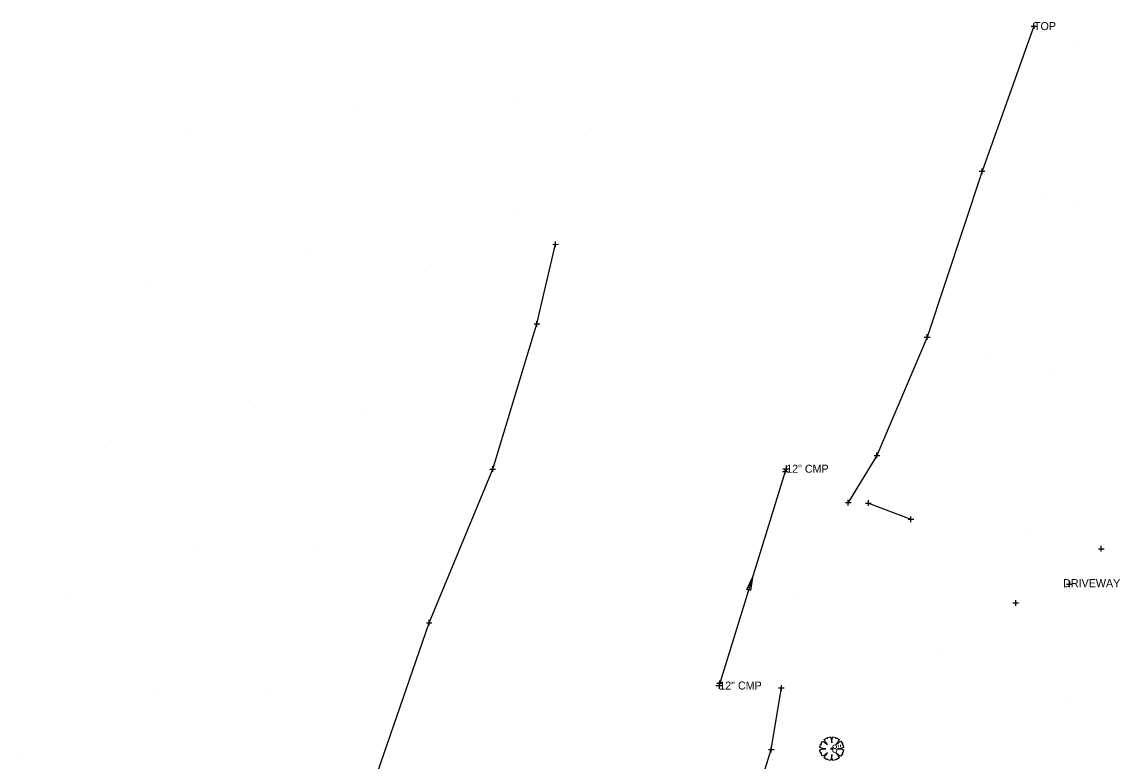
# Model space of a CAD drawing. Extents: x 1733239 to 1734352, y 466612 to 468622.
# Drawn here: x 1733811.3 to 1734058.3, y 467992.2 to 468158.3 of the extents above; entities that cross this region are included whole.
import ezdxf

# ---------------------------------------------------------------- set-up
doc = ezdxf.new("R2010")
doc.units = 0
for name, color, linetype in [('Default', 7, 'Continuous'), ('S_Terrain_Flow_Arrows', 7, 'Continuous'), ('S_Terrain_Holes', 7, 'Continuous'), ('S_Terrain_Imported_Contours', 7, 'Continuous'), ('S_Terrain_Major_Contours', 7, 'Continuous'), ('S_Terrain_Minor_Contours', 7, 'Continuous'), ('S_Terrain_Minor_Contours_Label', 7, 'Continuous'), ('S_Traffic_Sign_SinglePost', 7, 'Continuous'), ('S_Trees_Bush_Line', 7, 'Continuous'), ('S_Utilities_Pole_StreetLight', 7, 'Continuous')]:
    doc.layers.add(name, color=color, linetype=linetype)

msp = doc.modelspace()

# ---------------------------------------------------------------- linework, layer by layer
at = {"layer": 'Default'}
for p, q in [((1733983.22, 468057.92), (1733983.22, 468057.92)), ((1733968.17, 468009.19), (1733968.17, 468009.19))]:
    msp.add_line(p, q, dxfattribs=at)
at = {"layer": 'S_Terrain_Flow_Arrows'}
msp.add_lwpolyline([(1733992.14, 467994.99), (1733991.45, 467995.04), (1733990.81, 467995.25), (1733990.97, 467995.94), (1733991.13, 467995.94), (1733991.08, 467996.16), (1733991.4, 467996.69), (1733991.93, 467996.42), (1733992.51, 467995.94), (1733992.03, 467996.53), (1733991.77, 467997.06), (1733992.3, 467997.38), (1733992.51, 467997.32), (1733992.51, 467997.48), (1733993.2, 467997.64), (1733993.41, 467997), (1733993.47, 467996.31), (1733993.52, 467997), (1733993.73, 467997.64), (1733994.42, 467997.48), (1733994.42, 467997.32), (1733994.63, 467997.38), (1733995.16, 467997.06), (1733994.9, 467996.53), (1733994.42, 467995.94), (1733995, 467996.42), (1733995.53, 467996.69), (1733995.85, 467996.16), (1733995.8, 467995.94), (1733995.96, 467995.94), (1733996.12, 467995.25), (1733995.48, 467995.04), (1733994.79, 467994.99), (1733995.48, 467994.94), (1733996.12, 467994.72), (1733995.96, 467994.03), (1733995.8, 467994.03), (1733995.85, 467993.82), (1733995.53, 467993.29), (1733995, 467993.56), (1733994.42, 467994.03), (1733994.9, 467993.45), (1733995.16, 467992.92), (1733994.63, 467992.6), (1733994.42, 467992.65), (1733994.42, 467992.5), (1733993.73, 467992.34), (1733993.52, 467992.97), (1733993.47, 467993.66), (1733993.41, 467992.97), (1733993.2, 467992.34), (1733992.51, 467992.5), (1733992.51, 467992.65), (1733992.3, 467992.6), (1733991.77, 467992.92), (1733992.03, 467993.45), (1733992.51, 467994.03), (1733991.93, 467993.56), (1733991.4, 467993.29), (1733991.08, 467993.82), (1733991.13, 467994.03), (1733990.97, 467994.03), (1733990.81, 467994.72), (1733991.45, 467994.94), (1733992.14, 467994.99)], dxfattribs=at)
msp.add_circle((1733993.47, 467994.99), 0.166, dxfattribs=at)
at = {"layer": 'S_Terrain_Holes'}
for points in [[(1734038.95, 468157.41), (1734027.27, 468124.78), (1734014.93, 468087.5), (1734003.63, 468060.91), (1733997.18, 468050.3)], [(1733853.36, 467859.67), (1733863.53, 467892.27), (1733873.85, 467924.74), (1733885.4, 467959.39), (1733891.32, 467989.61), (1733902.91, 468023.32), (1733917.22, 468057.86), (1733927.15, 468090.49), (1733931.35, 468108.36)], [(1733949.51, 467895.49), (1733959.79, 467928.95), (1733970.61, 467965.17), (1733979.86, 467994.8), (1733982.14, 468008.65)]]:
    msp.add_lwpolyline(points, dxfattribs=at)
at = {"layer": 'S_Terrain_Imported_Contours'}
msp.add_lwpolyline([(1733983, 468057.32), (1733968.28, 468009.7)], dxfattribs=at)
at = {"layer": 'S_Terrain_Major_Contours'}
for p, q in [((1734049.25, 468154.03), (1734049.25, 468154.03)), ((1733922.15, 468140.86), (1733922.15, 468140.86)), ((1733886.42, 468138.46), (1733886.42, 468138.46)), ((1733848.19, 468133.54), (1733848.19, 468133.54)), ((1733939.41, 468134.3), (1733939.41, 468134.3)), ((1734041.18, 468118.74), (1734041.18, 468118.74)), ((1734047.6, 468117.7), (1734047.6, 468117.7)), ((1733921.95, 468115.26), (1733921.95, 468115.26)), ((1733874.9, 468106.77), (1733874.9, 468106.77)), ((1733901.91, 468102.25), (1733901.91, 468102.25)), ((1733840.3, 468099.4), (1733840.3, 468099.4)), ((1734028.89, 468084.09), (1734028.89, 468084.09)), ((1734042.8, 468079.69), (1734042.8, 468079.69)), ((1733862.33, 468073.19), (1733862.33, 468073.19)), ((1733888.4, 468070.35), (1733888.4, 468070.35)), ((1733831.51, 468064.26), (1733831.51, 468064.26)), ((1734037.92, 468044.55), (1734037.92, 468044.55)), ((1733851.11, 468039.67), (1733851.11, 468039.67)), ((1733878.05, 468040.13), (1733878.05, 468040.13)), ((1733822.47, 468029.22), (1733822.47, 468029.22)), ((1733985.14, 468028.73), (1733985.14, 468028.73)), ((1734018.25, 468016.95), (1734018.25, 468016.95)), ((1733840.84, 468007.27), (1733840.84, 468007.27)), ((1733866.3, 468008.18), (1733866.3, 468008.18)), ((1734047.08, 468006.09), (1734047.08, 468006.09)), ((1733811.32, 467994.06), (1733811.32, 467994.06))]:
    msp.add_line(p, q, dxfattribs=at)
at = {"layer": 'S_Terrain_Minor_Contours'}
for p, q in [((1734038.96, 468156.77), (1734038.95, 468158.05)), ((1734038.32, 468157.41), (1734039.59, 468157.41)), ((1734038.95, 468157.41), (1734038.95, 468157.41)), ((1734026.63, 468124.78), (1734027.91, 468124.79)), ((1734027.27, 468124.15), (1734027.27, 468125.42)), ((1734027.27, 468124.78), (1734027.27, 468124.78)), ((1733930.72, 468108.35), (1733931.99, 468108.36)), ((1733931.35, 468107.72), (1733931.35, 468108.99)), ((1733931.35, 468108.36), (1733931.35, 468108.36)), ((1733927.15, 468089.85), (1733927.15, 468091.12)), ((1733926.51, 468090.49), (1733927.78, 468090.49)), ((1733927.15, 468090.49), (1733927.15, 468090.49)), ((1734014.29, 468087.5), (1734015.57, 468087.5)), ((1734014.93, 468086.87), (1734014.93, 468088.14)), ((1734014.93, 468087.5), (1734014.93, 468087.5)), ((1734003.63, 468060.27), (1734003.63, 468061.54)), ((1734003, 468060.91), (1734004.27, 468060.91)), ((1734003.63, 468060.91), (1734003.63, 468060.91)), ((1733916.58, 468057.86), (1733917.85, 468057.86)), ((1733917.22, 468057.22), (1733917.22, 468058.49)), ((1733917.22, 468057.86), (1733917.22, 468057.86)), ((1733982.36, 468057.32), (1733983.64, 468057.33)), ((1733983, 468056.69), (1733983, 468057.96)), ((1733983, 468057.32), (1733983, 468057.32)), ((1733996.54, 468050.3), (1733997.81, 468050.3)), ((1733997.18, 468049.67), (1733997.17, 468050.94)), ((1733997.18, 468050.3), (1733997.18, 468050.3)), ((1734001.08, 468050.19), (1734002.35, 468050.2)), ((1734001.72, 468049.56), (1734001.72, 468050.83)), ((1734001.72, 468050.19), (1734001.72, 468050.19)), ((1734011.26, 468045.92), (1734011.26, 468047.2)), ((1734010.62, 468046.56), (1734011.9, 468046.56)), ((1734011.26, 468046.56), (1734011.26, 468046.56)), ((1734053.47, 468039.92), (1734054.74, 468039.92)), ((1734054.1, 468039.28), (1734054.1, 468040.56)), ((1734054.1, 468039.92), (1734054.1, 468039.92)), ((1734046.28, 468031.94), (1734047.55, 468031.95)), ((1734046.92, 468031.31), (1734046.92, 468032.58)), ((1734046.92, 468031.95), (1734046.92, 468031.95)), ((1734034.23, 468027.77), (1734035.5, 468027.77)), ((1734034.87, 468027.13), (1734034.87, 468028.41)), ((1734034.87, 468027.77), (1734034.87, 468027.77)), ((1733902.28, 468023.31), (1733903.55, 468023.32)), ((1733902.91, 468022.68), (1733902.91, 468023.95)), ((1733902.91, 468023.32), (1733902.91, 468023.32)), ((1733967.64, 468009.69), (1733968.92, 468009.7)), ((1733968.28, 468009.06), (1733968.28, 468010.33)), ((1733968.28, 468009.7), (1733968.28, 468009.7)), ((1733981.5, 468008.64), (1733982.77, 468008.65)), ((1733982.14, 468008.01), (1733982.14, 468009.28)), ((1733982.14, 468008.65), (1733982.14, 468008.65)), ((1733979.23, 467994.8), (1733980.5, 467994.8)), ((1733979.86, 467994.17), (1733979.86, 467995.44)), ((1733979.86, 467994.8), (1733979.86, 467994.8))]:
    msp.add_line(p, q, dxfattribs=at)
at = {"layer": 'S_Terrain_Minor_Contours_Label'}
for p, q in [((1733982.47, 468057.92), (1733983.97, 468057.92)), ((1733983.22, 468058.67), (1733983.22, 468057.17)), ((1733968.17, 468009.94), (1733968.17, 468008.44)), ((1733967.42, 468009.19), (1733968.92, 468009.19))]:
    msp.add_line(p, q, dxfattribs=at)
at = {"layer": 'S_Trees_Bush_Line'}
msp.add_lwpolyline([(1734001.72, 468050.19), (1734011.26, 468046.56)], dxfattribs=at)
at = {"layer": 'S_Utilities_Pole_StreetLight'}
msp.add_line((1733975.64, 468033.51), (1733975.64, 468033.51), dxfattribs=at)
msp.add_lwpolyline([(1733975.64, 468033.51), (1733975.19, 468030.54), (1733974.34, 468030.81)], close=True, dxfattribs=at)

# ---------------------------------------------------------------- texts
at = {"layer": 'S_Traffic_Sign_SinglePost'}
for s, p in [('TOP', (1734038.95, 468156.51)), ('12" CMP', (1733983.22, 468057.02)), ('DRIVEWAY', (1734045.52, 468031.3)), ('12" CMP', (1733968.17, 468008.29)), ('8"', (1733993.47, 467994.09))]:
    msp.add_text(s, height=1.8, dxfattribs=at).set_placement(p)

doc.saveas('drawing.dxf')
